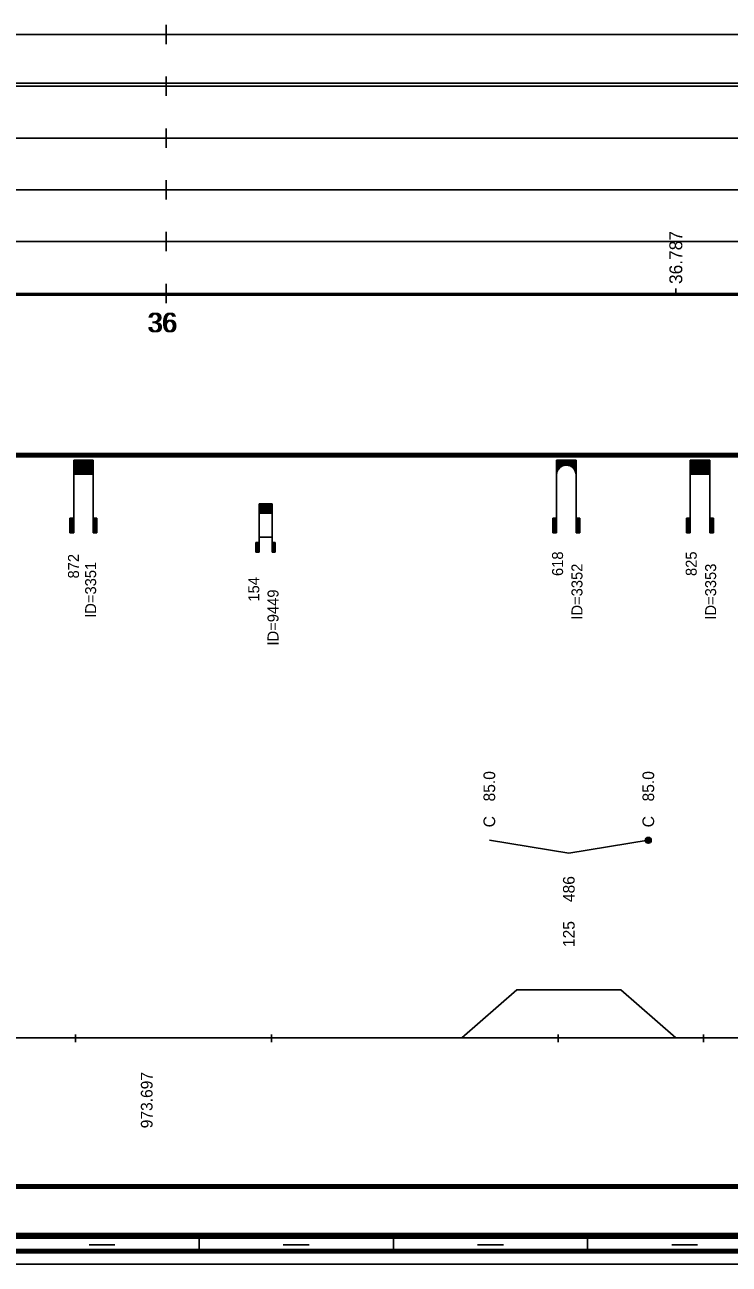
# Model space of a CAD drawing. Extents: x 2 to 10148, y 0 to 380.
# Drawn here: x 3878.1 to 3986.9, y 0 to 191.5 of the extents above; entities that cross this region are included whole.
import ezdxf

# ---------------------------------------------------------------- set-up
doc = ezdxf.new("R2010")
doc.units = 0
for name, color, linetype in [('CARA_S_OBJEKTY', 7, 'Continuous'), ('KRIV1_CARA', 7, 'Continuous'), ('KRIV1_TEXT', 7, 'Continuous'), ('OBJEKTY_TEXT', 7, 'Continuous'), ('OBJEKTY_TVAR', 7, 'Continuous'), ('RAM', 7, 'Continuous'), ('RYCHL_A', 7, 'Continuous'), ('RYCHL_RASTR', 7, 'Continuous'), ('RYCHL_STAN', 7, 'Continuous'), ('STAN_CARA', 7, 'Continuous'), ('STANIC_ZMEN_V', 7, 'Continuous')]:
    doc.layers.add(name, color=color, linetype=linetype)

msp = doc.modelspace()

# ---------------------------------------------------------------- linework, layer by layer
for p, q in [((3885.9, 35.51), (3885.9, 34.32)), ((3916.17, 35.51), (3916.17, 34.32)), ((3960.44, 35.51), (3960.44, 34.32)), ((3982.9, 35.51), (3982.9, 34.32))]:
    msp.add_line(p, q)
at = {"layer": 'CARA_S_OBJEKTY'}
for p, q in [((3155.54, 125.25), (4045.76, 125.25)), ((3155.54, 125), (4045.76, 125)), ((3155.54, 124.75), (4045.76, 124.75))]:
    msp.add_line(p, q, dxfattribs=at)
at = {"layer": 'KRIV1_CARA'}
for p, q in [((3945.58, 35), (3954.08, 42.41)), ((3954.08, 42.41), (3970.14, 42.41)), ((3970.14, 42.41), (3978.64, 35)), ((3155.54, 35), (4045.76, 35))]:
    msp.add_line(p, q, dxfattribs=at)
at = {"layer": 'KRIV1_TEXT'}
for q in [(3949.83, 65.5), (3974.39, 65.5)]:
    msp.add_line((3962.11, 63.5), q, dxfattribs=at)
for radius in [0.45, 0.3, 0.15]:
    msp.add_circle((3974.39, 65.5), radius, dxfattribs=at)
at = {"layer": 'OBJEKTY_TVAR'}
for p, q in [((3885.62, 124.25), (3888.62, 124.25)), ((3885.62, 113), (3885.62, 124.25)), ((3885.62, 124.17), (3888.62, 124.17)), ((3885.62, 124.1), (3888.62, 124.1)), ((3885.62, 124.02), (3888.62, 124.02)), ((3885.62, 123.95), (3888.62, 123.95)), ((3885.62, 123.87), (3888.62, 123.87)), ((3885.62, 123.8), (3888.62, 123.8)), ((3885.62, 123.72), (3888.62, 123.72)), ((3885.62, 123.65), (3888.62, 123.65)), ((3885.62, 123.57), (3888.62, 123.57)), ((3885.62, 123.5), (3888.62, 123.5)), ((3885.62, 123.42), (3888.62, 123.42)), ((3885.62, 123.35), (3888.62, 123.35)), ((3885.62, 123.27), (3888.62, 123.27)), ((3885.62, 123.2), (3888.62, 123.2)), ((3885.62, 123.12), (3888.62, 123.12)), ((3885.62, 123.05), (3888.62, 123.05)), ((3885.62, 122.97), (3888.62, 122.97)), ((3885.62, 122.9), (3888.62, 122.9)), ((3885.62, 122.82), (3888.62, 122.82)), ((3885.62, 122.75), (3888.62, 122.75)), ((3885.62, 122.67), (3888.62, 122.67)), ((3885.62, 122.6), (3888.62, 122.6)), ((3888.62, 124.25), (3888.62, 113)), ((3960.22, 113), (3960.22, 124.25)), ((3963.22, 124.25), (3960.22, 124.25)), ((3960.22, 124.17), (3963.22, 124.17)), ((3960.22, 124.1), (3963.22, 124.1)), ((3960.22, 124.02), (3963.22, 124.02)), ((3960.22, 123.95), (3963.22, 123.95)), ((3960.22, 123.87), (3963.22, 123.87)), ((3960.22, 123.8), (3963.22, 123.8)), ((3960.22, 123.72), (3963.22, 123.72)), ((3960.22, 123.65), (3963.22, 123.65)), ((3960.22, 123.57), (3963.22, 123.57)), ((3960.22, 123.5), (3963.22, 123.5)), ((3960.22, 123.42), (3961.38, 123.42)), ((3960.22, 123.35), (3961.14, 123.35)), ((3960.22, 123.27), (3960.99, 123.27)), ((3960.22, 123.2), (3960.87, 123.2)), ((3960.22, 123.12), (3960.77, 123.12)), ((3960.22, 123.05), (3960.68, 123.05)), ((3960.22, 122.97), (3960.61, 122.97)), ((3960.22, 122.9), (3960.55, 122.9)), ((3960.22, 122.82), (3960.49, 122.82)), ((3960.22, 122.75), (3960.44, 122.75)), ((3960.22, 122.67), (3960.4, 122.67)), ((3960.22, 122.6), (3960.36, 122.6)), ((3960.3, 122.46), (3960.37, 122.61)), ((3960.37, 122.61), (3960.44, 122.75)), ((3960.44, 122.75), (3960.55, 122.9)), ((3960.55, 122.9), (3960.68, 123.05)), ((3960.68, 123.05), (3960.76, 123.12)), ((3960.76, 123.12), (3960.86, 123.19)), ((3960.86, 123.19), (3960.99, 123.27)), ((3960.99, 123.27), (3961.14, 123.35)), ((3961.14, 123.35), (3961.38, 123.42)), ((3961.38, 123.42), (3961.59, 123.46)), ((3961.59, 123.46), (3961.84, 123.46)), ((3961.84, 123.46), (3961.98, 123.44)), ((3961.98, 123.44), (3962.06, 123.42)), ((3962.06, 123.42), (3963.22, 123.42)), ((3962.06, 123.42), (3962.3, 123.35)), ((3962.3, 123.35), (3963.22, 123.35)), ((3962.3, 123.35), (3962.45, 123.27)), ((3962.45, 123.27), (3963.22, 123.27)), ((3962.45, 123.27), (3962.57, 123.2)), ((3962.57, 123.2), (3963.22, 123.2)), ((3962.57, 123.2), (3962.67, 123.12)), ((3962.67, 123.12), (3963.22, 123.12)), ((3962.67, 123.12), (3962.76, 123.05)), ((3962.76, 123.05), (3963.22, 123.05)), ((3962.76, 123.05), (3962.83, 122.97)), ((3962.83, 122.97), (3963.22, 122.97)), ((3962.83, 122.97), (3962.89, 122.9)), ((3962.89, 122.9), (3963.21, 122.9)), ((3962.89, 122.9), (3962.95, 122.82)), ((3962.95, 122.82), (3963.22, 122.82)), ((3962.95, 122.82), (3963.04, 122.67)), ((3963, 122.75), (3963.22, 122.75)), ((3963.04, 122.67), (3963.22, 122.67)), ((3963.04, 122.67), (3963.11, 122.52)), ((3963.08, 122.6), (3963.22, 122.6)), ((3963.22, 124.25), (3963.22, 113)), ((3980.87, 124.25), (3983.87, 124.25)), ((3980.87, 113), (3980.87, 124.25)), ((3980.87, 124.17), (3983.87, 124.17)), ((3980.87, 124.1), (3983.87, 124.1)), ((3980.87, 124.02), (3983.87, 124.02)), ((3980.87, 123.95), (3983.87, 123.95)), ((3980.87, 123.87), (3983.87, 123.87)), ((3980.87, 123.8), (3983.87, 123.8)), ((3980.87, 123.72), (3983.87, 123.72)), ((3980.87, 123.65), (3983.87, 123.65)), ((3980.87, 123.57), (3983.87, 123.57)), ((3980.87, 123.5), (3983.87, 123.5)), ((3980.87, 123.42), (3983.87, 123.42)), ((3980.87, 123.35), (3983.87, 123.35)), ((3980.87, 123.27), (3983.87, 123.27)), ((3980.87, 123.2), (3983.87, 123.2)), ((3980.87, 123.12), (3983.87, 123.12)), ((3980.87, 123.05), (3983.87, 123.05)), ((3980.87, 122.97), (3983.87, 122.97)), ((3980.87, 122.9), (3983.87, 122.9)), ((3980.87, 122.82), (3983.87, 122.82)), ((3980.87, 122.75), (3983.87, 122.75)), ((3980.87, 122.67), (3983.87, 122.67)), ((3980.87, 122.6), (3983.87, 122.6)), ((3983.87, 124.25), (3983.87, 113)), ((3885.62, 122.52), (3888.62, 122.52)), ((3885.62, 122.45), (3888.62, 122.45)), ((3885.62, 122.37), (3888.62, 122.37)), ((3885.62, 122.3), (3888.62, 122.3)), ((3885.62, 122.22), (3888.62, 122.22)), ((3885.62, 122.15), (3888.62, 122.15)), ((3885.62, 122.07), (3888.62, 122.07)), ((3960.22, 122.52), (3960.33, 122.52)), ((3960.22, 122.45), (3960.3, 122.45)), ((3960.22, 122.37), (3960.28, 122.37)), ((3960.22, 122.3), (3960.26, 122.3)), ((3960.22, 122.22), (3960.24, 122.22)), ((3960.22, 122.15), (3960.23, 122.15)), ((3960.22, 121.97), (3960.23, 122.11)), ((3960.23, 122.11), (3960.25, 122.28)), ((3960.25, 122.28), (3960.3, 122.46)), ((3963.11, 122.52), (3963.22, 122.52)), ((3963.11, 122.52), (3963.16, 122.37)), ((3963.14, 122.45), (3963.22, 122.45)), ((3963.16, 122.37), (3963.22, 122.37)), ((3963.16, 122.37), (3963.2, 122.22)), ((3963.18, 122.3), (3963.22, 122.3)), ((3963.2, 122.22), (3963.22, 122.22)), ((3963.2, 122.22), (3963.22, 121.97)), ((3963.21, 122.15), (3963.22, 122.15)), ((3980.87, 122.52), (3983.87, 122.52)), ((3980.87, 122.45), (3983.87, 122.45)), ((3980.87, 122.37), (3983.87, 122.37)), ((3980.87, 122.3), (3983.87, 122.3)), ((3980.87, 122.22), (3983.87, 122.22)), ((3980.87, 122.15), (3983.87, 122.15)), ((3980.87, 122.07), (3983.87, 122.07)), ((3914.26, 110), (3914.26, 117.5)), ((3914.26, 117.5), (3916.26, 117.5)), ((3914.26, 117.45), (3916.26, 117.45)), ((3914.26, 117.4), (3916.26, 117.4)), ((3914.26, 117.35), (3916.26, 117.35)), ((3914.26, 117.3), (3916.26, 117.3)), ((3914.26, 117.25), (3916.26, 117.25)), ((3914.26, 117.2), (3916.26, 117.2)), ((3914.26, 117.15), (3916.26, 117.15)), ((3914.26, 117.1), (3916.26, 117.1)), ((3914.26, 117.05), (3916.26, 117.05)), ((3914.26, 117), (3916.26, 117)), ((3914.26, 116.95), (3916.26, 116.95)), ((3914.26, 116.9), (3916.26, 116.9)), ((3914.26, 116.85), (3916.26, 116.85)), ((3916.26, 117.5), (3916.26, 110)), ((3885.02, 115.25), (3885.02, 113)), ((3885.02, 115.25), (3885.62, 115.25)), ((3885.09, 115.25), (3885.09, 113)), ((3885.17, 115.25), (3885.17, 113)), ((3885.24, 115.25), (3885.24, 113)), ((3885.32, 115.25), (3885.32, 113)), ((3885.39, 115.25), (3885.39, 113)), ((3885.47, 115.25), (3885.47, 113)), ((3885.54, 115.25), (3885.54, 113)), ((3889.22, 115.25), (3888.62, 115.25)), ((3888.7, 115.25), (3888.7, 113)), ((3888.77, 115.25), (3888.77, 113)), ((3888.85, 115.25), (3888.85, 113)), ((3888.92, 115.25), (3888.92, 113)), ((3889, 115.25), (3889, 113)), ((3889.07, 115.25), (3889.07, 113)), ((3889.15, 115.25), (3889.15, 113)), ((3889.22, 115.25), (3889.22, 113)), ((3914.26, 116.8), (3916.26, 116.8)), ((3914.26, 116.75), (3916.26, 116.75)), ((3914.26, 116.7), (3916.26, 116.7)), ((3914.26, 116.65), (3916.26, 116.65)), ((3914.26, 116.6), (3916.26, 116.6)), ((3914.26, 116.55), (3916.26, 116.55)), ((3914.26, 116.5), (3916.26, 116.5)), ((3914.26, 116.45), (3916.26, 116.45)), ((3914.26, 116.4), (3916.26, 116.4)), ((3914.26, 116.35), (3916.26, 116.35)), ((3914.26, 116.3), (3916.26, 116.3)), ((3914.26, 116.25), (3916.26, 116.25)), ((3914.26, 116.2), (3916.26, 116.2)), ((3914.26, 116.15), (3916.26, 116.15)), ((3914.26, 116.1), (3916.26, 116.1)), ((3914.26, 116.05), (3916.26, 116.05)), ((3959.62, 115.25), (3960.22, 115.25)), ((3959.62, 115.25), (3959.62, 113)), ((3959.69, 115.25), (3959.69, 113)), ((3959.77, 115.25), (3959.77, 113)), ((3959.84, 115.25), (3959.84, 113)), ((3959.92, 115.25), (3959.92, 113)), ((3959.99, 115.25), (3959.99, 113)), ((3960.07, 115.25), (3960.07, 113)), ((3960.14, 115.25), (3960.14, 113)), ((3963.82, 115.25), (3963.22, 115.25)), ((3963.3, 115.25), (3963.3, 113)), ((3963.37, 115.25), (3963.37, 113)), ((3963.45, 115.25), (3963.45, 113)), ((3963.52, 115.25), (3963.52, 113)), ((3963.6, 115.25), (3963.6, 113)), ((3963.67, 115.25), (3963.67, 113)), ((3963.75, 115.25), (3963.75, 113)), ((3963.82, 115.25), (3963.82, 113)), ((3980.27, 115.25), (3980.27, 113)), ((3980.27, 115.25), (3980.87, 115.25)), ((3980.34, 115.25), (3980.34, 113)), ((3980.42, 115.25), (3980.42, 113)), ((3980.49, 115.25), (3980.49, 113)), ((3980.57, 115.25), (3980.57, 113)), ((3980.64, 115.25), (3980.64, 113)), ((3980.72, 115.25), (3980.72, 113)), ((3980.79, 115.25), (3980.79, 113)), ((3984.47, 115.25), (3983.87, 115.25)), ((3983.95, 115.25), (3983.95, 113)), ((3984.02, 115.25), (3984.02, 113)), ((3984.1, 115.25), (3984.1, 113)), ((3984.17, 115.25), (3984.17, 113)), ((3984.25, 115.25), (3984.25, 113)), ((3984.32, 115.25), (3984.32, 113)), ((3984.4, 115.25), (3984.4, 113)), ((3984.47, 115.25), (3984.47, 113)), ((3885.62, 113), (3885.02, 113)), ((3888.62, 113), (3889.22, 113)), ((3960.22, 113), (3959.62, 113)), ((3963.22, 113), (3963.82, 113)), ((3980.87, 113), (3980.27, 113)), ((3983.87, 113), (3984.47, 113)), ((3913.76, 111.5), (3914.26, 111.5)), ((3913.76, 111.5), (3913.76, 110)), ((3913.81, 111.5), (3913.81, 110)), ((3913.86, 111.5), (3913.86, 110)), ((3913.91, 111.5), (3913.91, 110)), ((3913.96, 111.5), (3913.96, 110)), ((3914.01, 111.5), (3914.01, 110)), ((3914.06, 111.5), (3914.06, 110)), ((3914.11, 111.5), (3914.11, 110)), ((3914.16, 111.5), (3914.16, 110)), ((3914.21, 111.5), (3914.21, 110)), ((3914.26, 112.31), (3916.26, 112.31)), ((3916.76, 111.5), (3916.26, 111.5)), ((3916.31, 111.5), (3916.31, 110)), ((3916.36, 111.5), (3916.36, 110)), ((3916.41, 111.5), (3916.41, 110)), ((3916.46, 111.5), (3916.46, 110)), ((3916.51, 111.5), (3916.51, 110)), ((3916.56, 111.5), (3916.56, 110)), ((3916.61, 111.5), (3916.61, 110)), ((3916.66, 111.5), (3916.66, 110)), ((3916.71, 111.5), (3916.71, 110)), ((3916.76, 111.5), (3916.76, 110)), ((3914.26, 110), (3913.76, 110)), ((3916.26, 110), (3916.76, 110))]:
    msp.add_line(p, q, dxfattribs=at)
at = {"layer": 'RAM'}
for p, q in [((3155.54, 4.75), (4045.76, 4.75)), ((3155.54, 4.5), (4045.76, 4.5)), ((3155.54, 4.25), (4045.76, 4.25)), ((3155.54, 4), (4045.76, 4)), ((3905, 2), (3905, 4)), ((3935, 2), (3935, 4)), ((3965, 2), (3965, 4)), ((3155.54, 2.25), (4045.76, 2.25)), ((3155.54, 2), (4045.76, 2)), ((3888, 3), (3892, 3)), ((3918, 3), (3922, 3)), ((3948, 3), (3952, 3)), ((3978, 3), (3982, 3)), ((3155.54, 1.75), (4045.76, 1.75)), ((3155.54, 0), (4045.76, 0))]:
    msp.add_line(p, q, dxfattribs=at)
at = {"layer": 'RYCHL_A'}
msp.add_line((3782.41, 182.5), (4046.42, 182.5), dxfattribs=at)
at = {"layer": 'RYCHL_RASTR'}
for p, q in [((3899.91, 188.5), (3899.91, 191.5)), ((3155.54, 190), (4046.94, 190)), ((3155.54, 182), (4047.3, 182)), ((3899.91, 180.5), (3899.91, 183.5)), ((3899.91, 172.5), (3899.91, 175.5)), ((3155.54, 174), (4047.27, 174)), ((3899.91, 164.5), (3899.91, 167.5)), ((3155.54, 166), (4047.1, 166)), ((3899.91, 156.5), (3899.91, 159.5)), ((3155.54, 158), (4047.25, 158)), ((3899.91, 148.5), (3899.91, 151.5)), ((3155.54, 150), (4045.76, 150)), ((3155.54, 149.75), (4045.76, 149.75))]:
    msp.add_line(p, q, dxfattribs=at)
at = {"layer": 'STAN_CARA'}
for p, q in [((3801.41, 12.25), (4045.76, 12.25)), ((3801.41, 12), (4045.76, 12)), ((3801.41, 12), (4045.76, 12)), ((3801.41, 11.75), (4045.76, 11.75))]:
    msp.add_line(p, q, dxfattribs=at)
at = {"layer": 'STANIC_ZMEN_V'}
msp.add_line((3978.64, 150), (3978.64, 150.75), dxfattribs=at)

# ---------------------------------------------------------------- texts
at = {"layer": 'KRIV1_TEXT'}
for s, p in [('85.0', (3950.73, 71.5)), ('85.0', (3975.29, 71.5)), ('C', (3950.73, 67.5)), ('C', (3975.29, 67.5)), ('486', (3963.01, 55.95)), ('125', (3963.01, 49)), ('973.697', (3897.8, 21))]:
    msp.add_text(s, height=1.8, rotation=90, dxfattribs=at).set_placement(p)
at = {"layer": 'OBJEKTY_TEXT'}
for s, p in [('872', (3886.44, 105.95)), ('618', (3961.22, 106.33)), ('825', (3981.87, 106.33)), ('ID=3351', (3889.09, 99.87)), ('ID=3352', (3964.22, 99.59)), ('ID=3353', (3984.87, 99.59)), ('154', (3914.29, 102.38)), ('ID=9449', (3917.26, 95.59))]:
    msp.add_text(s, height=1.7, rotation=90, dxfattribs=at).set_placement(p)
at = {"layer": 'RYCHL_STAN'}
for p in [(3896.97, 144), (3897.22, 144)]:
    msp.add_text('36', height=3, dxfattribs=at).set_placement(p)
at = {"layer": 'STANIC_ZMEN_V'}
msp.add_text('36.787', height=2, rotation=90, dxfattribs=at).set_placement((3979.64, 151.45))

doc.saveas('drawing.dxf')
